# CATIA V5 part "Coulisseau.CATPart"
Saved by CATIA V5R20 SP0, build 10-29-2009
Part number: Coulisseau
Bounding box of the stored display mesh (mm): x -30 to 40, y 20 to 50, z -20 to 30
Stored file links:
  D:\thinkmotion-MPB\Dropbox\IAO_2011\MMS_GR3\aweinling\aweinling\Coulisseau.CATPart
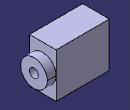
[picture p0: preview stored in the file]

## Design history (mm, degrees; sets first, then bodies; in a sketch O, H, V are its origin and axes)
Parameters
  D_Trou = 10 mm
  D_Pivot = 30 mm
Body1 (main body)
  Sketch1 on yz-plane, origin (0, 0, 0), H (0, 1, 0), V (0, 0, 1)
    line L1 (20, 30) -> (50, 30)
    line L2 (50, 30) -> (50, -20)
    line L3 (50, -20) -> (20, -20)
    line L4 (20, -20) -> (20, 30)
    length L2 = 50
    length L1 = 30
    horizontal: L1 H, L3 H
    vertical: L2 V, L4 V
  Pad1: profile Sketch1, direction (1, 0, 0), length 30, opposite side length 30
  Sketch2 on yz-plane, origin (0, 0, 0), H (0, 1, 0), V (0, 0, 1)
    circle A1 centre (35, 5) radius 15
    point P1 (35, 5)
    reference projected line E1 (50, 30) -> (20, 30) from edge [face of Pad1 from Sketch1.L1 | end face of Pad1]
    reference projected line E2 (50, -20) -> (50, 30) from edge [face of Pad1 from Sketch1.L2 | end face of Pad1]
    distance P1 E1 = 25
    distance P1 E2 = 15
    radius A1 = 15 {= D_Pivot /2}
  Pad2: profile Sketch2, direction (1, 0, 0), length 40, opposite side length -30
  Sketch3 on end face of Pad2, origin (40, 35, 5), H (0, 1, 0), V (0, 0, 1)
    point P1 (0, 0)
  Hole1: placed by Sketch3, at (40, 35, 5) direction (-1, 0, 0), diameter 10 {= D_Trou}, through (limit type 6)
  Point1: type Center, Curve edge [end face of Pad2 | face of Hole1]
